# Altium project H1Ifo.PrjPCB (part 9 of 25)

## Sheet IfoIsc4.SchDoc: D1800185
size C; Engineer: Daniel Sigg; DocumentNumber: 8; Revision: 4; SheetNumber: 8; SheetTotal: 11
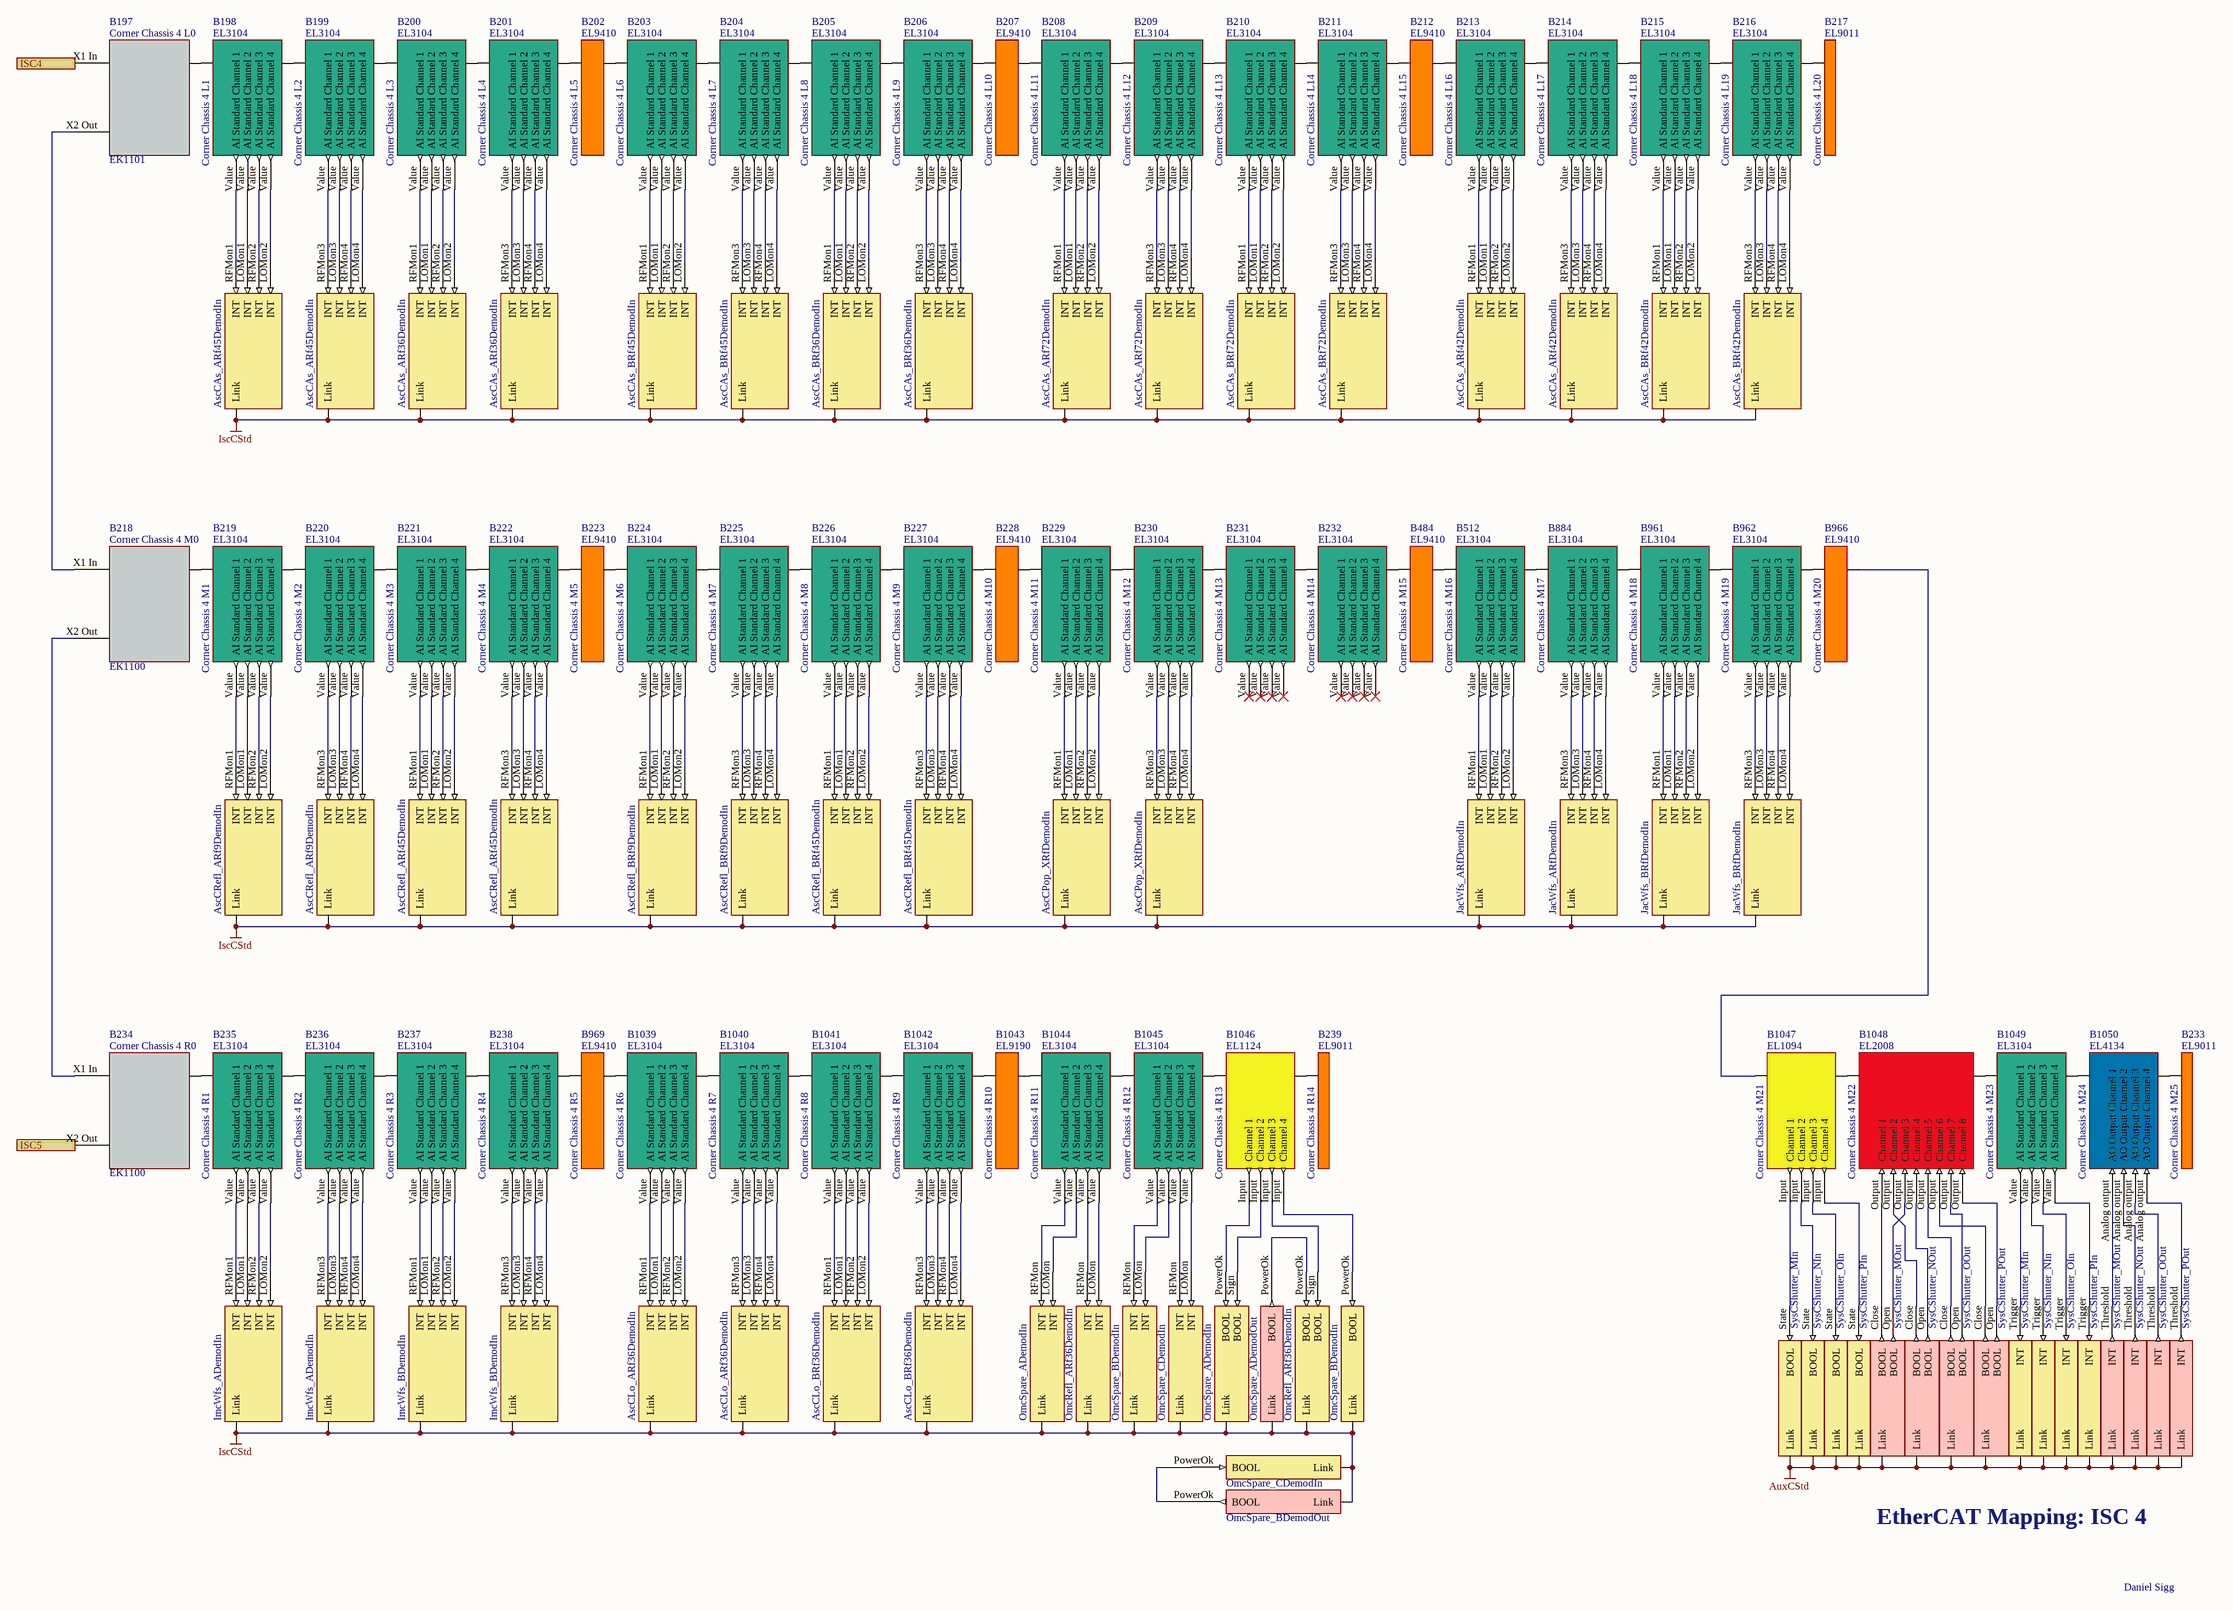
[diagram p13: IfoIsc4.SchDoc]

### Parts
B197  Corner Chassis 4 L0  Part Number: EK1101  (mechanical)
B198  Corner Chassis 4 L1  Part Number: EL3104  (mechanical)
B199  Corner Chassis 4 L2  Part Number: EL3104  (mechanical)
B200  Corner Chassis 4 L3  Part Number: EL3104  (mechanical)
B201  Corner Chassis 4 L4  Part Number: EL3104  (mechanical)
B202  Corner Chassis 4 L5  Part Number: EL9410  (mechanical)
B203  Corner Chassis 4 L6  Part Number: EL3104  (mechanical)
B204  Corner Chassis 4 L7  Part Number: EL3104  (mechanical)
B205  Corner Chassis 4 L8  Part Number: EL3104  (mechanical)
B206  Corner Chassis 4 L9  Part Number: EL3104  (mechanical)
B207  Corner Chassis 4 L10  Part Number: EL9410  (mechanical)
B208  Corner Chassis 4 L11  Part Number: EL3104  (mechanical)
B209  Corner Chassis 4 L12  Part Number: EL3104  (mechanical)
B210  Corner Chassis 4 L13  Part Number: EL3104  (mechanical)
B211  Corner Chassis 4 L14  Part Number: EL3104  (mechanical)
B212  Corner Chassis 4 L15  Part Number: EL9410  (mechanical)
B213  Corner Chassis 4 L16  Part Number: EL3104  (mechanical)
B214  Corner Chassis 4 L17  Part Number: EL3104  (mechanical)
B215  Corner Chassis 4 L18  Part Number: EL3104  (mechanical)
B216  Corner Chassis 4 L19  Part Number: EL3104  (mechanical)
B217  Corner Chassis 4 L20  Part Number: EL9011  (mechanical)
B218  Corner Chassis 4 M0  Part Number: EK1100  (mechanical)
B219  Corner Chassis 4 M1  Part Number: EL3104  (mechanical)
B220  Corner Chassis 4 M2  Part Number: EL3104  (mechanical)
B221  Corner Chassis 4 M3  Part Number: EL3104  (mechanical)
B222  Corner Chassis 4 M4  Part Number: EL3104  (mechanical)
B223  Corner Chassis 4 M5  Part Number: EL9410  (mechanical)
B224  Corner Chassis 4 M6  Part Number: EL3104  (mechanical)
B225  Corner Chassis 4 M7  Part Number: EL3104  (mechanical)
B226  Corner Chassis 4 M8  Part Number: EL3104  (mechanical)
B227  Corner Chassis 4 M9  Part Number: EL3104  (mechanical)
B228  Corner Chassis 4 M10  Part Number: EL9410  (mechanical)
B229  Corner Chassis 4 M11  Part Number: EL3104  (mechanical)
B230  Corner Chassis 4 M12  Part Number: EL3104  (mechanical)
B231  Corner Chassis 4 M13  Part Number: EL3104  (mechanical)
B232  Corner Chassis 4 M14  Part Number: EL3104  (mechanical)
B233  Corner Chassis 4 M25  Part Number: EL9011  (mechanical)
B234  Corner Chassis 4 R0  Part Number: EK1100  (mechanical)
B235  Corner Chassis 4 R1  Part Number: EL3104  (mechanical)
B236  Corner Chassis 4 R2  Part Number: EL3104  (mechanical)
B237  Corner Chassis 4 R3  Part Number: EL3104  (mechanical)
B238  Corner Chassis 4 R4  Part Number: EL3104  (mechanical)
B239  Corner Chassis 4 R14  Part Number: EL9011  (mechanical)
B484  Corner Chassis 4 M15  Part Number: EL9410  (mechanical)
B512  Corner Chassis 4 M16  Part Number: EL3104  (mechanical)
B884  Corner Chassis 4 M17  Part Number: EL3104  (mechanical)
B961  Corner Chassis 4 M18  Part Number: EL3104  (mechanical)
B962  Corner Chassis 4 M19  Part Number: EL3104  (mechanical)
B966  Corner Chassis 4 M20  Part Number: EL9410  (mechanical)
B969  Corner Chassis 4 R5  Part Number: EL9410  (mechanical)
B1039  Corner Chassis 4 R6  Part Number: EL3104  (mechanical)
B1040  Corner Chassis 4 R7  Part Number: EL3104  (mechanical)
B1041  Corner Chassis 4 R8  Part Number: EL3104  (mechanical)
B1042  Corner Chassis 4 R9  Part Number: EL3104  (mechanical)
B1043  Corner Chassis 4 R10  Part Number: EL9190  (mechanical)
B1044  Corner Chassis 4 R11  Part Number: EL3104  (mechanical)
B1045  Corner Chassis 4 R12  Part Number: EL3104  (mechanical)
B1046  Corner Chassis 4 R13  Part Number: EL1124  (mechanical)
B1047  Corner Chassis 4 M21  Part Number: EL1094  (mechanical)
B1048  Corner Chassis 4 M22  Part Number: EL2008  (mechanical)
B1049  Corner Chassis 4 M23  Part Number: EL3104  (mechanical)
B1050  Corner Chassis 4 M24  Part Number: EL4134  (mechanical)
V300  AscCAs_ARf45DemodIn  (parts A,B of 2)  (no BOM)
V301  AscCAs_ARf36DemodIn  (parts A,B of 2)  (no BOM)
V302  AscCAs_BRf45DemodIn  (parts A,B of 2)  (no BOM)
V321  AscCAs_BRf36DemodIn  (parts A,B of 2)  (no BOM)
V322  AscCAs_ARf72DemodIn  (parts A,B of 2)  (no BOM)
V323  AscCAs_BRf72DemodIn  (parts A,B of 2)  (no BOM)
V324  AscCAs_ARf42DemodIn  (parts A,B of 2)  (no BOM)
V326  AscCAs_BRf42DemodIn  (parts A,B of 2)  (no BOM)
V327  AscCRefl_ARf9DemodIn  (parts A,B of 2)  (no BOM)
V329  AscCRefl_ARf45DemodIn  (parts A,B of 2)  (no BOM)
V330  AscCRefl_BRf9DemodIn  (parts A,B of 2)  (no BOM)
V331  AscCRefl_BRf45DemodIn  (parts A,B of 2)  (no BOM)
V332  AscCPop_XRfDemodIn  (parts A,B of 2)  (no BOM)
V333  ImcWfs_ADemodIn  (parts A,B of 2)  (no BOM)
V334  ImcWfs_BDemodIn  (parts A,B of 2)  (no BOM)
V494  OmcSpare_ADemodOut  (no BOM)
V875  OmcSpare_BDemodOut  (no BOM)
V878  JacWfs_ARfDemodIn  (parts A,B of 2)  (no BOM)
V879  JacWfs_BRfDemodIn  (parts A,B of 2)  (no BOM)
V880  AscCLo_ARf36DemodIn  (parts A,B of 2)  (no BOM)
V881  AscCLo_BRf36DemodIn  (parts A,B of 2)  (no BOM)
V882  OmcSpare_ADemodIn  (parts A,B of 2)  (no BOM)
V883  OmcRefl_ARf36DemodIn  (parts A,B of 2)  (no BOM)
V884  OmcSpare_BDemodIn  (parts A,B of 2)  (no BOM)
V885  OmcSpare_CDemodIn  (parts A,B of 2)  (no BOM)
V886  SysCShutter_MIn  (parts A,B of 2)  (no BOM)
V887  SysCShutter_NIn  (parts A,B of 2)  (no BOM)
V888  SysCShutter_OIn  (parts A,B of 2)  (no BOM)
V889  SysCShutter_PIn  (parts A,B of 2)  (no BOM)
V890  SysCShutter_MOut  (parts A,B of 2)  (no BOM)
V891  SysCShutter_NOut  (parts A,B of 2)  (no BOM)
V892  SysCShutter_OOut  (parts A,B of 2)  (no BOM)
V893  SysCShutter_POut  (parts A,B of 2)  (no BOM)

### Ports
ISC4, ISC5

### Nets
AuxCStd: V886.0(Link) V886.1(Link) V887.0(Link) V887.1(Link) V888.0(Link) V888.1(Link) V889.0(Link) V889.1(Link) V890.0(Link) V890.1(Link) V891.0(Link) V891.1(Link) V892.0(Link) V892.1(Link) V893.0(Link) V893.1(Link)
IscCStd: V300.0(Link) V300.1(Link) V301.0(Link) V301.1(Link) V302.0(Link) V302.1(Link) V321.0(Link) V321.1(Link) V322.0(Link) V322.1(Link) V323.0(Link) V323.1(Link) V324.0(Link) V324.1(Link) V326.0(Link) V326.1(Link) V327.0(Link) V327.1(Link) V329.0(Link) V329.1(Link) V330.0(Link) V330.1(Link) V331.0(Link) V331.1(Link) V332.0(Link) V332.1(Link) V333.0(Link) V333.1(Link) V334.0(Link) V334.1(Link) V494.?1(Link) V875.?1(Link) V878.0(Link) V878.1(Link) V879.0(Link) V879.1(Link) V880.0(Link) V880.1(Link) V881.0(Link) V881.1(Link) V882.0(Link) V882.1(Link) V883.0(Link) V883.1(Link) V884.0(Link) V884.1(Link) V885.0(Link) V885.1(Link)
NetB175_X2 Out: B197.X1_In(A) ; port ISC4
NetB197_Ebus: B197.Ebus(B) B198.Ebus(A)
NetB197_X2 Out: B197.X2_Out(C) B218.X1_In(A)
NetB198_Ebus: B198.Ebus(B) B199.Ebus(A)
NetB198_Value: B198.Value(AI_Standard_Channel_1) V300.RFMon1(INT)
NetB198_Value: B198.Value(AI_Standard_Channel_2) V300.LOMon1(INT)  [a separate net that carries the same name]
NetB198_Value: B198.Value(AI_Standard_Channel_3) V300.RFMon2(INT)  [a separate net that carries the same name]
NetB198_Value: B198.Value(AI_Standard_Channel_4) V300.LOMon2(INT)  [a separate net that carries the same name]
NetB199_Ebus: B199.Ebus(B) B200.Ebus(A)
NetB199_Value: B199.Value(AI_Standard_Channel_1) V300.RFMon3(INT)
NetB199_Value: B199.Value(AI_Standard_Channel_2) V300.LOMon3(INT)  [a separate net that carries the same name]
NetB199_Value: B199.Value(AI_Standard_Channel_3) V300.RFMon4(INT)  [a separate net that carries the same name]
NetB199_Value: B199.Value(AI_Standard_Channel_4) V300.LOMon4(INT)  [a separate net that carries the same name]
NetB200_Ebus: B200.Ebus(B) B201.Ebus(A)
NetB200_Value: B200.Value(AI_Standard_Channel_1) V301.RFMon1(INT)
NetB200_Value: B200.Value(AI_Standard_Channel_2) V301.LOMon1(INT)  [a separate net that carries the same name]
NetB200_Value: B200.Value(AI_Standard_Channel_3) V301.RFMon2(INT)  [a separate net that carries the same name]
NetB200_Value: B200.Value(AI_Standard_Channel_4) V301.LOMon2(INT)  [a separate net that carries the same name]
NetB201_Ebus: B201.Ebus(B) B202.Ebus(A)
NetB201_Value: B201.Value(AI_Standard_Channel_1) V301.RFMon3(INT)
NetB201_Value: B201.Value(AI_Standard_Channel_2) V301.LOMon3(INT)  [a separate net that carries the same name]
NetB201_Value: B201.Value(AI_Standard_Channel_3) V301.RFMon4(INT)  [a separate net that carries the same name]
NetB201_Value: B201.Value(AI_Standard_Channel_4) V301.LOMon4(INT)  [a separate net that carries the same name]
NetB202_Ebus: B202.Ebus(B) B203.Ebus(A)
NetB203_Ebus: B203.Ebus(B) B204.Ebus(A)
NetB203_Value: B203.Value(AI_Standard_Channel_1) V302.RFMon1(INT)
NetB203_Value: B203.Value(AI_Standard_Channel_2) V302.LOMon1(INT)  [a separate net that carries the same name]
NetB203_Value: B203.Value(AI_Standard_Channel_3) V302.RFMon2(INT)  [a separate net that carries the same name]
NetB203_Value: B203.Value(AI_Standard_Channel_4) V302.LOMon2(INT)  [a separate net that carries the same name]
NetB204_Ebus: B204.Ebus(B) B205.Ebus(A)
NetB204_Value: B204.Value(AI_Standard_Channel_1) V302.RFMon3(INT)
NetB204_Value: B204.Value(AI_Standard_Channel_2) V302.LOMon3(INT)  [a separate net that carries the same name]
NetB204_Value: B204.Value(AI_Standard_Channel_3) V302.RFMon4(INT)  [a separate net that carries the same name]
NetB204_Value: B204.Value(AI_Standard_Channel_4) V302.LOMon4(INT)  [a separate net that carries the same name]
NetB205_Ebus: B205.Ebus(B) B206.Ebus(A)
NetB205_Value: B205.Value(AI_Standard_Channel_1) V321.RFMon1(INT)
NetB205_Value: B205.Value(AI_Standard_Channel_2) V321.LOMon1(INT)  [a separate net that carries the same name]
NetB205_Value: B205.Value(AI_Standard_Channel_3) V321.RFMon2(INT)  [a separate net that carries the same name]
NetB205_Value: B205.Value(AI_Standard_Channel_4) V321.LOMon2(INT)  [a separate net that carries the same name]
NetB206_Ebus: B206.Ebus(B) B207.Ebus(A)
NetB206_Value: B206.Value(AI_Standard_Channel_1) V321.RFMon3(INT)
NetB206_Value: B206.Value(AI_Standard_Channel_2) V321.LOMon3(INT)  [a separate net that carries the same name]
NetB206_Value: B206.Value(AI_Standard_Channel_3) V321.RFMon4(INT)  [a separate net that carries the same name]
NetB206_Value: B206.Value(AI_Standard_Channel_4) V321.LOMon4(INT)  [a separate net that carries the same name]
NetB207_Ebus: B207.Ebus(B) B208.Ebus(A)
NetB208_Ebus: B208.Ebus(B) B209.Ebus(A)
NetB208_Value: B208.Value(AI_Standard_Channel_1) V322.RFMon1(INT)
NetB208_Value: B208.Value(AI_Standard_Channel_2) V322.LOMon1(INT)  [a separate net that carries the same name]
NetB208_Value: B208.Value(AI_Standard_Channel_3) V322.RFMon2(INT)  [a separate net that carries the same name]
NetB208_Value: B208.Value(AI_Standard_Channel_4) V322.LOMon2(INT)  [a separate net that carries the same name]
NetB209_Ebus: B209.Ebus(B) B210.Ebus(A)
NetB209_Value: B209.Value(AI_Standard_Channel_1) V322.RFMon3(INT)
NetB209_Value: B209.Value(AI_Standard_Channel_2) V322.LOMon3(INT)  [a separate net that carries the same name]
NetB209_Value: B209.Value(AI_Standard_Channel_3) V322.RFMon4(INT)  [a separate net that carries the same name]
NetB209_Value: B209.Value(AI_Standard_Channel_4) V322.LOMon4(INT)  [a separate net that carries the same name]
NetB210_Ebus: B210.Ebus(B) B211.Ebus(A)
NetB210_Value: B210.Value(AI_Standard_Channel_1) V323.RFMon1(INT)
NetB210_Value: B210.Value(AI_Standard_Channel_2) V323.LOMon1(INT)  [a separate net that carries the same name]
NetB210_Value: B210.Value(AI_Standard_Channel_3) V323.RFMon2(INT)  [a separate net that carries the same name]
NetB210_Value: B210.Value(AI_Standard_Channel_4) V323.LOMon2(INT)  [a separate net that carries the same name]
NetB211_Ebus: B211.Ebus(B) B212.Ebus(A)
NetB211_Value: B211.Value(AI_Standard_Channel_1) V323.RFMon3(INT)
NetB211_Value: B211.Value(AI_Standard_Channel_2) V323.LOMon3(INT)  [a separate net that carries the same name]
NetB211_Value: B211.Value(AI_Standard_Channel_3) V323.RFMon4(INT)  [a separate net that carries the same name]
NetB211_Value: B211.Value(AI_Standard_Channel_4) V323.LOMon4(INT)  [a separate net that carries the same name]
NetB212_Ebus: B212.Ebus(B) B213.Ebus(A)
NetB213_Ebus: B213.Ebus(B) B214.Ebus(A)
NetB213_Value: B213.Value(AI_Standard_Channel_1) V324.RFMon1(INT)
NetB213_Value: B213.Value(AI_Standard_Channel_2) V324.LOMon1(INT)  [a separate net that carries the same name]
NetB213_Value: B213.Value(AI_Standard_Channel_3) V324.RFMon2(INT)  [a separate net that carries the same name]
NetB213_Value: B213.Value(AI_Standard_Channel_4) V324.LOMon2(INT)  [a separate net that carries the same name]
NetB214_Ebus: B214.Ebus(B) B215.Ebus(A)
NetB214_Value: B214.Value(AI_Standard_Channel_1) V324.RFMon3(INT)
NetB214_Value: B214.Value(AI_Standard_Channel_2) V324.LOMon3(INT)  [a separate net that carries the same name]
NetB214_Value: B214.Value(AI_Standard_Channel_3) V324.RFMon4(INT)  [a separate net that carries the same name]
NetB214_Value: B214.Value(AI_Standard_Channel_4) V324.LOMon4(INT)  [a separate net that carries the same name]
NetB215_Ebus: B215.Ebus(B) B216.Ebus(A)
NetB215_Value: B215.Value(AI_Standard_Channel_1) V326.RFMon1(INT)
NetB215_Value: B215.Value(AI_Standard_Channel_2) V326.LOMon1(INT)  [a separate net that carries the same name]
NetB215_Value: B215.Value(AI_Standard_Channel_3) V326.RFMon2(INT)  [a separate net that carries the same name]
NetB215_Value: B215.Value(AI_Standard_Channel_4) V326.LOMon2(INT)  [a separate net that carries the same name]
NetB216_Ebus: B216.Ebus(B) B217.Ebus(A)
NetB216_Value: B216.Value(AI_Standard_Channel_1) V326.RFMon3(INT)
NetB216_Value: B216.Value(AI_Standard_Channel_2) V326.LOMon3(INT)  [a separate net that carries the same name]
NetB216_Value: B216.Value(AI_Standard_Channel_3) V326.RFMon4(INT)  [a separate net that carries the same name]
NetB216_Value: B216.Value(AI_Standard_Channel_4) V326.LOMon4(INT)  [a separate net that carries the same name]
NetB218_Ebus: B218.Ebus(B) B219.Ebus(A)
NetB218_X2 Out: B218.X2_Out(C) B234.X1_In(A)
NetB219_Ebus: B219.Ebus(B) B220.Ebus(A)
NetB219_Value: B219.Value(AI_Standard_Channel_1) V327.RFMon1(INT)
NetB219_Value: B219.Value(AI_Standard_Channel_2) V327.LOMon1(INT)  [a separate net that carries the same name]
NetB219_Value: B219.Value(AI_Standard_Channel_3) V327.RFMon2(INT)  [a separate net that carries the same name]
NetB219_Value: B219.Value(AI_Standard_Channel_4) V327.LOMon2(INT)  [a separate net that carries the same name]
NetB220_Ebus: B220.Ebus(B) B221.Ebus(A)
NetB220_Value: B220.Value(AI_Standard_Channel_1) V327.RFMon3(INT)
NetB220_Value: B220.Value(AI_Standard_Channel_2) V327.LOMon3(INT)  [a separate net that carries the same name]
NetB220_Value: B220.Value(AI_Standard_Channel_3) V327.RFMon4(INT)  [a separate net that carries the same name]
NetB220_Value: B220.Value(AI_Standard_Channel_4) V327.LOMon4(INT)  [a separate net that carries the same name]
NetB221_Ebus: B221.Ebus(B) B222.Ebus(A)
NetB221_Value: B221.Value(AI_Standard_Channel_1) V329.RFMon1(INT)
NetB221_Value: B221.Value(AI_Standard_Channel_2) V329.LOMon1(INT)  [a separate net that carries the same name]
NetB221_Value: B221.Value(AI_Standard_Channel_3) V329.RFMon2(INT)  [a separate net that carries the same name]
NetB221_Value: B221.Value(AI_Standard_Channel_4) V329.LOMon2(INT)  [a separate net that carries the same name]
NetB222_Ebus: B222.Ebus(B) B223.Ebus(A)
NetB222_Value: B222.Value(AI_Standard_Channel_1) V329.RFMon3(INT)
NetB222_Value: B222.Value(AI_Standard_Channel_2) V329.LOMon3(INT)  [a separate net that carries the same name]
NetB222_Value: B222.Value(AI_Standard_Channel_3) V329.RFMon4(INT)  [a separate net that carries the same name]
NetB222_Value: B222.Value(AI_Standard_Channel_4) V329.LOMon4(INT)  [a separate net that carries the same name]
NetB223_Ebus: B223.Ebus(B) B224.Ebus(A)
NetB224_Ebus: B224.Ebus(B) B225.Ebus(A)
NetB224_Value: B224.Value(AI_Standard_Channel_1) V330.RFMon1(INT)
NetB224_Value: B224.Value(AI_Standard_Channel_2) V330.LOMon1(INT)  [a separate net that carries the same name]
NetB224_Value: B224.Value(AI_Standard_Channel_3) V330.RFMon2(INT)  [a separate net that carries the same name]
NetB224_Value: B224.Value(AI_Standard_Channel_4) V330.LOMon2(INT)  [a separate net that carries the same name]
NetB225_Ebus: B225.Ebus(B) B226.Ebus(A)
NetB225_Value: B225.Value(AI_Standard_Channel_1) V330.RFMon3(INT)
NetB225_Value: B225.Value(AI_Standard_Channel_2) V330.LOMon3(INT)  [a separate net that carries the same name]
NetB225_Value: B225.Value(AI_Standard_Channel_3) V330.RFMon4(INT)  [a separate net that carries the same name]
NetB225_Value: B225.Value(AI_Standard_Channel_4) V330.LOMon4(INT)  [a separate net that carries the same name]
NetB226_Ebus: B226.Ebus(B) B227.Ebus(A)
NetB226_Value: B226.Value(AI_Standard_Channel_1) V331.RFMon1(INT)
NetB226_Value: B226.Value(AI_Standard_Channel_2) V331.LOMon1(INT)  [a separate net that carries the same name]
NetB226_Value: B226.Value(AI_Standard_Channel_3) V331.RFMon2(INT)  [a separate net that carries the same name]
NetB226_Value: B226.Value(AI_Standard_Channel_4) V331.LOMon2(INT)  [a separate net that carries the same name]
NetB227_Ebus: B227.Ebus(B) B228.Ebus(A)
NetB227_Value: B227.Value(AI_Standard_Channel_1) V331.RFMon3(INT)
NetB227_Value: B227.Value(AI_Standard_Channel_2) V331.LOMon3(INT)  [a separate net that carries the same name]
NetB227_Value: B227.Value(AI_Standard_Channel_3) V331.RFMon4(INT)  [a separate net that carries the same name]
NetB227_Value: B227.Value(AI_Standard_Channel_4) V331.LOMon4(INT)  [a separate net that carries the same name]
NetB228_Ebus: B228.Ebus(B) B229.Ebus(A)
NetB229_Ebus: B229.Ebus(B) B230.Ebus(A)
NetB229_Value: B229.Value(AI_Standard_Channel_1) V332.RFMon1(INT)
NetB229_Value: B229.Value(AI_Standard_Channel_2) V332.LOMon1(INT)  [a separate net that carries the same name]
NetB229_Value: B229.Value(AI_Standard_Channel_3) V332.RFMon2(INT)  [a separate net that carries the same name]
NetB229_Value: B229.Value(AI_Standard_Channel_4) V332.LOMon2(INT)  [a separate net that carries the same name]
NetB230_Ebus: B230.Ebus(B) B231.Ebus(A)
NetB230_Value: B230.Value(AI_Standard_Channel_1) V332.RFMon3(INT)
NetB230_Value: B230.Value(AI_Standard_Channel_2) V332.LOMon3(INT)  [a separate net that carries the same name]
NetB230_Value: B230.Value(AI_Standard_Channel_3) V332.RFMon4(INT)  [a separate net that carries the same name]
NetB230_Value: B230.Value(AI_Standard_Channel_4) V332.LOMon4(INT)  [a separate net that carries the same name]
NetB231_Ebus: B231.Ebus(B) B232.Ebus(A)
NetB232_Ebus: B232.Ebus(B) B484.Ebus(A)
NetB233_Ebus: B233.Ebus(A) B1050.Ebus(B)
NetB234_Ebus: B234.Ebus(B) B235.Ebus(A)
NetB234_X2 Out: B234.X2_Out(C) ; port ISC5
NetB235_Ebus: B235.Ebus(B) B236.Ebus(A)
NetB235_Value: B235.Value(AI_Standard_Channel_1) V333.RFMon1(INT)
NetB235_Value: B235.Value(AI_Standard_Channel_2) V333.LOMon1(INT)  [a separate net that carries the same name]
NetB235_Value: B235.Value(AI_Standard_Channel_3) V333.RFMon2(INT)  [a separate net that carries the same name]
NetB235_Value: B235.Value(AI_Standard_Channel_4) V333.LOMon2(INT)  [a separate net that carries the same name]
NetB236_Ebus: B236.Ebus(B) B237.Ebus(A)
NetB236_Value: B236.Value(AI_Standard_Channel_1) V333.RFMon3(INT)
NetB236_Value: B236.Value(AI_Standard_Channel_2) V333.LOMon3(INT)  [a separate net that carries the same name]
NetB236_Value: B236.Value(AI_Standard_Channel_3) V333.RFMon4(INT)  [a separate net that carries the same name]
NetB236_Value: B236.Value(AI_Standard_Channel_4) V333.LOMon4(INT)  [a separate net that carries the same name]
NetB237_Ebus: B237.Ebus(B) B238.Ebus(A)
NetB237_Value: B237.Value(AI_Standard_Channel_1) V334.RFMon1(INT)
NetB237_Value: B237.Value(AI_Standard_Channel_2) V334.LOMon1(INT)  [a separate net that carries the same name]
NetB237_Value: B237.Value(AI_Standard_Channel_3) V334.RFMon2(INT)  [a separate net that carries the same name]
NetB237_Value: B237.Value(AI_Standard_Channel_4) V334.LOMon2(INT)  [a separate net that carries the same name]
NetB238_Ebus: B238.Ebus(B) B969.Ebus(A)
NetB238_Value: B238.Value(AI_Standard_Channel_1) V334.RFMon3(INT)
NetB238_Value: B238.Value(AI_Standard_Channel_2) V334.LOMon3(INT)  [a separate net that carries the same name]
NetB238_Value: B238.Value(AI_Standard_Channel_3) V334.RFMon4(INT)  [a separate net that carries the same name]
NetB238_Value: B238.Value(AI_Standard_Channel_4) V334.LOMon4(INT)  [a separate net that carries the same name]
NetB239_Ebus: B239.Ebus(A) B1046.Ebus(B)
NetB484_Ebus: B484.Ebus(B) B512.Ebus(A)
NetB512_Ebus: B512.Ebus(B) B884.Ebus(A)
NetB512_Value: B512.Value(AI_Standard_Channel_1) V878.RFMon1(INT)
NetB512_Value: B512.Value(AI_Standard_Channel_2) V878.LOMon1(INT)  [a separate net that carries the same name]
NetB512_Value: B512.Value(AI_Standard_Channel_3) V878.RFMon2(INT)  [a separate net that carries the same name]
NetB512_Value: B512.Value(AI_Standard_Channel_4) V878.LOMon2(INT)  [a separate net that carries the same name]
NetB884_Ebus: B884.Ebus(B) B961.Ebus(A)
NetB884_Value: B884.Value(AI_Standard_Channel_1) V878.RFMon3(INT)
NetB884_Value: B884.Value(AI_Standard_Channel_2) V878.LOMon3(INT)  [a separate net that carries the same name]
NetB884_Value: B884.Value(AI_Standard_Channel_3) V878.RFMon4(INT)  [a separate net that carries the same name]
NetB884_Value: B884.Value(AI_Standard_Channel_4) V878.LOMon4(INT)  [a separate net that carries the same name]
NetB961_Ebus: B961.Ebus(B) B962.Ebus(A)
NetB961_Value: B961.Value(AI_Standard_Channel_1) V879.RFMon1(INT)
NetB961_Value: B961.Value(AI_Standard_Channel_2) V879.LOMon1(INT)  [a separate net that carries the same name]
NetB961_Value: B961.Value(AI_Standard_Channel_3) V879.RFMon2(INT)  [a separate net that carries the same name]
NetB961_Value: B961.Value(AI_Standard_Channel_4) V879.LOMon2(INT)  [a separate net that carries the same name]
NetB962_Ebus: B962.Ebus(B) B966.Ebus(A)
NetB962_Value: B962.Value(AI_Standard_Channel_1) V879.RFMon3(INT)
NetB962_Value: B962.Value(AI_Standard_Channel_2) V879.LOMon3(INT)  [a separate net that carries the same name]
NetB962_Value: B962.Value(AI_Standard_Channel_3) V879.RFMon4(INT)  [a separate net that carries the same name]
NetB962_Value: B962.Value(AI_Standard_Channel_4) V879.LOMon4(INT)  [a separate net that carries the same name]
NetB966_Ebus: B966.Ebus(B) B1047.Ebus(A)
NetB969_Ebus: B969.Ebus(B) B1039.Ebus(A)
NetB1039_Ebus: B1039.Ebus(B) B1040.Ebus(A)
NetB1039_Value: B1039.Value(AI_Standard_Channel_1) V880.RFMon1(INT)
NetB1039_Value: B1039.Value(AI_Standard_Channel_2) V880.LOMon1(INT)  [a separate net that carries the same name]
NetB1039_Value: B1039.Value(AI_Standard_Channel_3) V880.RFMon2(INT)  [a separate net that carries the same name]
NetB1039_Value: B1039.Value(AI_Standard_Channel_4) V880.LOMon2(INT)  [a separate net that carries the same name]
NetB1040_Ebus: B1040.Ebus(B) B1041.Ebus(A)
NetB1040_Value: B1040.Value(AI_Standard_Channel_1) V880.RFMon3(INT)
NetB1040_Value: B1040.Value(AI_Standard_Channel_2) V880.LOMon3(INT)  [a separate net that carries the same name]
NetB1040_Value: B1040.Value(AI_Standard_Channel_3) V880.RFMon4(INT)  [a separate net that carries the same name]
NetB1040_Value: B1040.Value(AI_Standard_Channel_4) V880.LOMon4(INT)  [a separate net that carries the same name]
NetB1041_Ebus: B1041.Ebus(B) B1042.Ebus(A)
NetB1041_Value: B1041.Value(AI_Standard_Channel_1) V881.RFMon1(INT)
NetB1041_Value: B1041.Value(AI_Standard_Channel_2) V881.LOMon1(INT)  [a separate net that carries the same name]
NetB1041_Value: B1041.Value(AI_Standard_Channel_3) V881.RFMon2(INT)  [a separate net that carries the same name]
NetB1041_Value: B1041.Value(AI_Standard_Channel_4) V881.LOMon2(INT)  [a separate net that carries the same name]
NetB1042_Ebus: B1042.Ebus(B) B1043.Ebus(A)
NetB1042_Value: B1042.Value(AI_Standard_Channel_1) V881.RFMon3(INT)
NetB1042_Value: B1042.Value(AI_Standard_Channel_2) V881.LOMon3(INT)  [a separate net that carries the same name]
NetB1042_Value: B1042.Value(AI_Standard_Channel_3) V881.RFMon4(INT)  [a separate net that carries the same name]
NetB1042_Value: B1042.Value(AI_Standard_Channel_4) V881.LOMon4(INT)  [a separate net that carries the same name]
NetB1043_Ebus: B1043.Ebus(B) B1044.Ebus(A)
NetB1044_Ebus: B1044.Ebus(B) B1045.Ebus(A)
NetB1044_Value: B1044.Value(AI_Standard_Channel_1) V882.RFMon(INT)
NetB1044_Value: B1044.Value(AI_Standard_Channel_2) V882.LOMon(INT)  [a separate net that carries the same name]
NetB1044_Value: B1044.Value(AI_Standard_Channel_3) V883.RFMon(INT)  [a separate net that carries the same name]
NetB1044_Value: B1044.Value(AI_Standard_Channel_4) V883.LOMon(INT)  [a separate net that carries the same name]
NetB1045_Ebus: B1045.Ebus(B) B1046.Ebus(A)
NetB1045_Value: B1045.Value(AI_Standard_Channel_1) V884.RFMon(INT)
NetB1045_Value: B1045.Value(AI_Standard_Channel_2) V884.LOMon(INT)  [a separate net that carries the same name]
NetB1045_Value: B1045.Value(AI_Standard_Channel_3) V885.RFMon(INT)  [a separate net that carries the same name]
NetB1045_Value: B1045.Value(AI_Standard_Channel_4) V885.LOMon(INT)  [a separate net that carries the same name]
NetB1046_Input: B1046.Input(Channel_1) V882.PowerOk(BOOL)
NetB1046_Input: B1046.Input(Channel_2) V882.Sign(BOOL)  [a separate net that carries the same name]
NetB1046_Input: B1046.Input(Channel_3) V883.Sign(BOOL)  [a separate net that carries the same name]
NetB1046_Input: B1046.Input(Channel_4) V884.PowerOk(BOOL)  [a separate net that carries the same name]
NetB1047_Ebus: B1047.Ebus(B) B1048.Ebus(A)
NetB1047_Input: B1047.Input(Channel_1) V886.State(BOOL)
NetB1047_Input: B1047.Input(Channel_2) V887.State(BOOL)  [a separate net that carries the same name]
NetB1047_Input: B1047.Input(Channel_3) V888.State(BOOL)  [a separate net that carries the same name]
NetB1047_Input: B1047.Input(Channel_4) V889.State(BOOL)  [a separate net that carries the same name]
NetB1048_Ebus: B1048.Ebus(B) B1049.Ebus(A)
NetB1048_Output: B1048.Output(Channel_1) V890.Close(BOOL)
NetB1048_Output: B1048.Output(Channel_2) V891.Close(BOOL)  [a separate net that carries the same name]
NetB1048_Output: B1048.Output(Channel_3) V890.Open(BOOL)  [a separate net that carries the same name]
NetB1048_Output: B1048.Output(Channel_4) V891.Open(BOOL)  [a separate net that carries the same name]
NetB1048_Output: B1048.Output(Channel_5) V892.Close(BOOL)  [a separate net that carries the same name]
NetB1048_Output: B1048.Output(Channel_6) V893.Close(BOOL)  [a separate net that carries the same name]
NetB1048_Output: B1048.Output(Channel_7) V892.Open(BOOL)  [a separate net that carries the same name]
NetB1048_Output: B1048.Output(Channel_8) V893.Open(BOOL)  [a separate net that carries the same name]
NetB1049_Ebus: B1049.Ebus(B) B1050.Ebus(A)
NetB1049_Value: B1049.Value(AI_Standard_Channel_1) V886.Trigger(INT)
NetB1049_Value: B1049.Value(AI_Standard_Channel_2) V887.Trigger(INT)  [a separate net that carries the same name]
NetB1049_Value: B1049.Value(AI_Standard_Channel_3) V888.Trigger(INT)  [a separate net that carries the same name]
NetB1049_Value: B1049.Value(AI_Standard_Channel_4) V889.Trigger(INT)  [a separate net that carries the same name]
NetB1050_Analog output: B1050.Analog_output(AO_Output_Channel_1) V890.Threshold(INT)
NetB1050_Analog output: B1050.Analog_output(AO_Output_Channel_2) V891.Threshold(INT)  [a separate net that carries the same name]
NetB1050_Analog output: B1050.Analog_output(AO_Output_Channel_3) V892.Threshold(INT)  [a separate net that carries the same name]
NetB1050_Analog output: B1050.Analog_output(AO_Output_Channel_4) V893.Threshold(INT)  [a separate net that carries the same name]
NetV494_PowerOk: V494.PowerOk(BOOL) V883.PowerOk(BOOL)
NetV875_PowerOk: V875.PowerOk(BOOL) V885.PowerOk(BOOL)

Not connected (* = marked no-connect by the designer): B231 Value(AI_Standard_Channel_1)*; B232 Value(AI_Standard_Channel_1)*

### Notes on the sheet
- EtherCAT Mapping: ISC 4
- Daniel Sigg

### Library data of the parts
B197 = CouplerEK1101: EtherCAT Coupler; Rail: Left; BoxNextB: IRGKQKYA; BoxNextC: MMNIINJF; BoxPrev: DISNVYMV; PortPrevFull: 1134/C; PortPrevShort: C 'X2 Out'; Fullname: TIID^Vertex ISC (EtherCAT)^Corner Chassis 4 L0 (EK1101); BoxPorts: Junction; BoxAddr: 1153; Disabled: False
B198 = TerminalEL3104: EtherCAT Terminal EL3104 4-chn Analog Input; Rail: Left; BoxNextB: DQNKWSCF; BoxPrev: YKWNQAOF; PortPrevFull: 1153/B; PortPrevShort: B; Fullname: TIID^Vertex ISC (EtherCAT)^Corner Chassis 4 L0 (EK1101)^Corner Chassis 4 L1 (EL3104); BoxAddr: 1154; Disabled: False
B199 = TerminalEL3104: EtherCAT Terminal EL3104 4-chn Analog Input; Rail: Left; BoxNextB: TADXUTLW; BoxPrev: IRGKQKYA; PortPrevFull: 1154/B; PortPrevShort: B; Fullname: TIID^Vertex ISC (EtherCAT)^Corner Chassis 4 L0 (EK1101)^Corner Chassis 4 L2 (EL3104); BoxAddr: 1155; Disabled: False
B200 = TerminalEL3104: EtherCAT Terminal EL3104 4-chn Analog Input; Rail: Left; BoxNextB: LMVFSTSA; BoxPrev: DQNKWSCF; PortPrevFull: 1155/B; PortPrevShort: B; Fullname: TIID^Vertex ISC (EtherCAT)^Corner Chassis 4 L0 (EK1101)^Corner Chassis 4 L3 (EL3104); BoxAddr: 1156; Disabled: False
B201 = TerminalEL3104: EtherCAT Terminal EL3104 4-chn Analog Input; Rail: Left; BoxNextB: THQIIDHL; BoxPrev: TADXUTLW; PortPrevFull: 1156/B; PortPrevShort: B; Fullname: TIID^Vertex ISC (EtherCAT)^Corner Chassis 4 L0 (EK1101)^Corner Chassis 4 L4 (EL3104); BoxAddr: 1157; Disabled: False
B202 B207 B212 = TerminalEL9410: EtherCAT Terminal EL9410 Power; Rail: Left; BoxNextB: CGWBNFDW; BoxPrev: XWFYBRPV; PortPrevFull: 1161/B; PortPrevShort: B; Fullname: TIID^Vertex ISC (EtherCAT)^Corner Chassis 4 L0 (EK1101)^Corner Chassis 4 L10 (EL9410); BoxAddr: 1162; Disabled: False
B203 = TerminalEL3104: EtherCAT Terminal EL3104 4-chn Analog Input; Rail: Left; BoxNextB: CWCPLCXA; BoxPrev: THQIIDHL; PortPrevFull: 1157/B; PortPrevShort: B; Fullname: TIID^Vertex ISC (EtherCAT)^Corner Chassis 4 L0 (EK1101)^Corner Chassis 4 L6 (EL3104); BoxAddr: 1158; Disabled: False
B204 = TerminalEL3104: EtherCAT Terminal EL3104 4-chn Analog Input; Rail: Left; BoxNextB: MSORJDLH; BoxPrev: WTOICCIA; PortPrevFull: 1158/B; PortPrevShort: B; Fullname: TIID^Vertex ISC (EtherCAT)^Corner Chassis 4 L0 (EK1101)^Corner Chassis 4 L7 (EL3104); BoxAddr: 1159; Disabled: False
B205 = TerminalEL3104: EtherCAT Terminal EL3104 4-chn Analog Input; Rail: Left; BoxNextB: XWFYBRPV; BoxPrev: CWCPLCXA; PortPrevFull: 1159/B; PortPrevShort: B; Fullname: TIID^Vertex ISC (EtherCAT)^Corner Chassis 4 L0 (EK1101)^Corner Chassis 4 L8 (EL3104); BoxAddr: 1160; Disabled: False
B206 = TerminalEL3104: EtherCAT Terminal EL3104 4-chn Analog Input; Rail: Left; BoxNextB: DGPRQBVX; BoxPrev: MSORJDLH; PortPrevFull: 1160/B; PortPrevShort: B; Fullname: TIID^Vertex ISC (EtherCAT)^Corner Chassis 4 L0 (EK1101)^Corner Chassis 4 L9 (EL3104); BoxAddr: 1161; Disabled: False
B208 = TerminalEL3104: EtherCAT Terminal EL3104 4-chn Analog Input; Rail: Left; BoxNextB: EPSPNJHV; BoxPrev: DGPRQBVX; PortPrevFull: 1162/B; PortPrevShort: B; Fullname: TIID^Vertex ISC (EtherCAT)^Corner Chassis 4 L0 (EK1101)^Corner Chassis 4 L11 (EL3104); BoxAddr: 1163; Disabled: False
B209 = TerminalEL3104: EtherCAT Terminal EL3104 4-chn Analog Input; Rail: Left; BoxNextB: PLJMPCCB; BoxPrev: CGWBNFDW; PortPrevFull: 1163/B; PortPrevShort: B; Fullname: TIID^Vertex ISC (EtherCAT)^Corner Chassis 4 L0 (EK1101)^Corner Chassis 4 L12 (EL3104); BoxAddr: 1164; Disabled: False
B210 = TerminalEL3104: EtherCAT Terminal EL3104 4-chn Analog Input; Rail: Left; BoxNextB: DGMJVBGJ; BoxPrev: EPSPNJHV; PortPrevFull: 1164/B; PortPrevShort: B; Fullname: TIID^Vertex ISC (EtherCAT)^Corner Chassis 4 L0 (EK1101)^Corner Chassis 4 L13 (EL3104); BoxAddr: 1165; Disabled: False
B211 = TerminalEL3104: EtherCAT Terminal EL3104 4-chn Analog Input; Rail: Left; BoxNextB: QQPRCIBY; BoxPrev: PLJMPCCB; PortPrevFull: 1165/B; PortPrevShort: B; Fullname: TIID^Vertex ISC (EtherCAT)^Corner Chassis 4 L0 (EK1101)^Corner Chassis 4 L14 (EL3104); BoxAddr: 1166; Disabled: False
B213 = TerminalEL3104: EtherCAT Terminal EL3104 4-chn Analog Input; Rail: Left; BoxNextB: IQOBSTDL; BoxPrev: QQPRCIBY; PortPrevFull: 1166/B; PortPrevShort: B; Fullname: TIID^Vertex ISC (EtherCAT)^Corner Chassis 4 L0 (EK1101)^Corner Chassis 4 L16 (EL3104); BoxAddr: 1167; Disabled: False
B214 = TerminalEL3104: EtherCAT Terminal EL3104 4-chn Analog Input; Rail: Left; BoxNextB: QEPTPBGN; BoxPrev: LULPDUJP; PortPrevFull: 1167/B; PortPrevShort: B; Fullname: TIID^Vertex ISC (EtherCAT)^Corner Chassis 4 L0 (EK1101)^Corner Chassis 4 L17 (EL3104); BoxAddr: 1168; Disabled: False
B215 = TerminalEL3104: EtherCAT Terminal EL3104 4-chn Analog Input; Rail: Left; BoxNextB: VSRORLKR; BoxPrev: IQOBSTDL; PortPrevFull: 1168/B; PortPrevShort: B; Fullname: TIID^Vertex ISC (EtherCAT)^Corner Chassis 4 L0 (EK1101)^Corner Chassis 4 L18 (EL3104); BoxAddr: 1169; Disabled: False
B216 = TerminalEL3104: EtherCAT Terminal EL3104 4-chn Analog Input; Rail: Left; BoxNextB: HTPFDEUL; BoxPrev: QEPTPBGN; PortPrevFull: 1169/B; PortPrevShort: B; Fullname: TIID^Vertex ISC (EtherCAT)^Corner Chassis 4 L0 (EK1101)^Corner Chassis 4 L19 (EL3104); BoxAddr: 1170; Disabled: False
B217 = TerminalEL9011: EtherCAT Terminal EL9011 End; BoxType: TerminalPassive; Rail: Left; BoxPrev: VSRORLKR; PortPrevShort: B; Fullname: TIID^Vertex ISC (EtherCAT)^Corner Chassis 4 L0 (EK1101)^Corner Chassis 4 L20 (EL9011); Disabled: False
B218 = CouplerEK1100: EtherCAT Coupler; Rail: Middle; BoxNextB: EXOFERFG; BoxNextC: YDPMJXXR; BoxPrev: YKWNQAOF; PortPrevFull: 1153/C; PortPrevShort: C 'X2 Out'; Fullname: TIID^Vertex ISC (EtherCAT)^Corner Chassis 4 M0 (EK1100); BoxPorts: Junction; BoxAddr: 1171; Disabled: False
B219 = TerminalEL3104: EtherCAT Terminal EL3104 4-chn Analog Input; Rail: Middle; BoxNextB: PCNADATP; BoxPrev: MMNIINJF; PortPrevFull: 1171/B; PortPrevShort: B; Fullname: TIID^Vertex ISC (EtherCAT)^Corner Chassis 4 M0 (EK1100)^Corner Chassis 4 M1 (EL3104); BoxAddr: 1172; Disabled: False
B220 = TerminalEL3104: EtherCAT Terminal EL3104 4-chn Analog Input; Rail: Middle; BoxNextB: GLSOVTQF; BoxPrev: EXOFERFG; PortPrevFull: 1172/B; PortPrevShort: B; Fullname: TIID^Vertex ISC (EtherCAT)^Corner Chassis 4 M0 (EK1100)^Corner Chassis 4 M2 (EL3104); BoxAddr: 1173; Disabled: False
B221 = TerminalEL3104: EtherCAT Terminal EL3104 4-chn Analog Input; Rail: Middle; BoxNextB: NACTFJPE; BoxPrev: PCNADATP; PortPrevFull: 1173/B; PortPrevShort: B; Fullname: TIID^Vertex ISC (EtherCAT)^Corner Chassis 4 M0 (EK1100)^Corner Chassis 4 M3 (EL3104); BoxAddr: 1174; Disabled: False
B222 = TerminalEL3104: EtherCAT Terminal EL3104 4-chn Analog Input; Rail: Middle; BoxNextB: KYQMILKW; BoxPrev: GLSOVTQF; PortPrevFull: 1174/B; PortPrevShort: B; Fullname: TIID^Vertex ISC (EtherCAT)^Corner Chassis 4 M0 (EK1100)^Corner Chassis 4 M4 (EL3104); BoxAddr: 1175; Disabled: False
B223 B228 B484 B966 B969 = TerminalEL9410: EtherCAT Terminal EL9410 Power; Rail: Middle; BoxNextB: MANUKDUB; BoxPrev: VILQHKDO; PortPrevFull: 1179/B; PortPrevShort: B; Fullname: TIID^Vertex ISC (EtherCAT)^Corner Chassis 4 M0 (EK1100)^Corner Chassis 4 M10 (EL9410); BoxAddr: 1180; Disabled: False
B224 B1039 = TerminalEL3104: EtherCAT Terminal EL3104 4-chn Analog Input; Rail: Middle; BoxNextB: HRRYATQS; BoxPrev: KYQMILKW; PortPrevFull: 1175/B; PortPrevShort: B; Fullname: TIID^Vertex ISC (EtherCAT)^Corner Chassis 4 M0 (EK1100)^Corner Chassis 4 M6 (EL3104); BoxAddr: 1176; Disabled: False
B225 B1040 = TerminalEL3104: EtherCAT Terminal EL3104 4-chn Analog Input; Rail: Middle; BoxNextB: RFTRKPHK; BoxPrev: AYMITKJK; PortPrevFull: 1176/B; PortPrevShort: B; Fullname: TIID^Vertex ISC (EtherCAT)^Corner Chassis 4 M0 (EK1100)^Corner Chassis 4 M7 (EL3104); BoxAddr: 1177; Disabled: False
B226 B1041 B1044 = TerminalEL3104: EtherCAT Terminal EL3104 4-chn Analog Input; Rail: Middle; BoxNextB: VILQHKDO; BoxPrev: HRRYATQS; PortPrevFull: 1177/B; PortPrevShort: B; Fullname: TIID^Vertex ISC (EtherCAT)^Corner Chassis 4 M0 (EK1100)^Corner Chassis 4 M8 (EL3104); BoxAddr: 1178; Disabled: False
B227 B1042 B1045 = TerminalEL3104: EtherCAT Terminal EL3104 4-chn Analog Input; Rail: Middle; BoxNextB: CTKHWEQP; BoxPrev: RFTRKPHK; PortPrevFull: 1178/B; PortPrevShort: B; Fullname: TIID^Vertex ISC (EtherCAT)^Corner Chassis 4 M0 (EK1100)^Corner Chassis 4 M9 (EL3104); BoxAddr: 1179; Disabled: False
B229 B512 = TerminalEL3104: EtherCAT Terminal EL3104 4-chn Analog Input; Rail: Middle; BoxNextB: CSDNENSF; BoxPrev: CTKHWEQP; PortPrevFull: 1180/B; PortPrevShort: B; Fullname: TIID^Vertex ISC (EtherCAT)^Corner Chassis 4 M0 (EK1100)^Corner Chassis 4 M11 (EL3104); BoxAddr: 1181; Disabled: False
B230 B884 = TerminalEL3104: EtherCAT Terminal EL3104 4-chn Analog Input; Rail: Middle; BoxNextB: SLIVPLEU; BoxPrev: MANUKDUB; PortPrevFull: 1181/B; PortPrevShort: B; Fullname: TIID^Vertex ISC (EtherCAT)^Corner Chassis 4 M0 (EK1100)^Corner Chassis 4 M12 (EL3104); BoxAddr: 1182; Disabled: False
B231 B961 = TerminalEL3104: EtherCAT Terminal EL3104 4-chn Analog Input; Rail: Middle; BoxNextB: SMFYHIJX; BoxPrev: CSDNENSF; PortPrevFull: 1182/B; PortPrevShort: B; Fullname: TIID^Vertex ISC (EtherCAT)^Corner Chassis 4 M0 (EK1100)^Corner Chassis 4 M13 (EL3104); BoxAddr: 1183; Disabled: False
B232 B962 B1049 = TerminalEL3104: EtherCAT Terminal EL3104 4-chn Analog Input; Rail: Middle; BoxNextB: PGIPFMSE; BoxPrev: SLIVPLEU; PortPrevFull: 1183/B; PortPrevShort: B; Fullname: TIID^Vertex ISC (EtherCAT)^Corner Chassis 4 M0 (EK1100)^Corner Chassis 4 M14 (EL3104); BoxAddr: 1184; Disabled: False
B233 = TerminalEL9011: EtherCAT Terminal EL9011 End; BoxType: TerminalPassive; Rail: Middle; BoxPrev: SMFYHIJX; PortPrevShort: B; Fullname: TIID^Vertex ISC (EtherCAT)^Corner Chassis 4 M0 (EK1100)^Corner Chassis 4 M15 (EL9011); Disabled: False
B234 = CouplerEK1100: EtherCAT Coupler; Rail: Right; BoxNextB: GLSLHGFW; BoxNextC: FCKUDXRC; BoxPrev: MMNIINJF; PortPrevFull: 1171/C; PortPrevShort: C 'X2 Out'; Fullname: TIID^Vertex ISC (EtherCAT)^Corner Chassis 4 R0 (EK1100); BoxPorts: Junction; BoxAddr: 1185; Disabled: False
B235 = TerminalEL3104: EtherCAT Terminal EL3104 4-chn Analog Input; Rail: Right; BoxNextB: APIJKXMM; BoxPrev: YDPMJXXR; PortPrevFull: 1185/B; PortPrevShort: B; Fullname: TIID^Vertex ISC (EtherCAT)^Corner Chassis 4 R0 (EK1100)^Corner Chassis 4 R1 (EL3104); BoxAddr: 1186; Disabled: False
B236 = TerminalEL3104: EtherCAT Terminal EL3104 4-chn Analog Input; Rail: Right; BoxNextB: WJTXISCD; BoxPrev: GLSLHGFW; PortPrevFull: 1186/B; PortPrevShort: B; Fullname: TIID^Vertex ISC (EtherCAT)^Corner Chassis 4 R0 (EK1100)^Corner Chassis 4 R2 (EL3104); BoxAddr: 1187; Disabled: False
B237 = TerminalEL3104: EtherCAT Terminal EL3104 4-chn Analog Input; Rail: Right; BoxNextB: TXKDSBLU; BoxPrev: APIJKXMM; PortPrevFull: 1187/B; PortPrevShort: B; Fullname: TIID^Vertex ISC (EtherCAT)^Corner Chassis 4 R0 (EK1100)^Corner Chassis 4 R3 (EL3104); BoxAddr: 1188; Disabled: False
B238 = TerminalEL3104: EtherCAT Terminal EL3104 4-chn Analog Input; Rail: Right; BoxNextB: SCGCHNEM; BoxPrev: WJTXISCD; PortPrevFull: 1188/B; PortPrevShort: B; Fullname: TIID^Vertex ISC (EtherCAT)^Corner Chassis 4 R0 (EK1100)^Corner Chassis 4 R4 (EL3104); BoxAddr: 1189; Disabled: False
B239 = TerminalEL9011: EtherCAT Terminal EL9011 End; BoxType: TerminalPassive; Rail: Right; BoxPrev: TXKDSBLU; PortPrevShort: B; Fullname: TIID^Vertex ISC (EtherCAT)^Corner Chassis 4 R0 (EK1100)^Corner Chassis 4 R5 (EL9011); Disabled: False
B1043 = TerminalEL9190: EtherCAT Terminal EL9190 Supply; BoxType: TerminalPassive; Rail: Middle; BoxNextB: NIFPYAGY; BoxPrev: AWJEIRBS; PortPrevShort: B; Fullname: TIID^Vertex ISC (EtherCAT)^Corner Chassis 5 M0 (EK1100)^Corner Chassis 5 M8 (EL9190); Disabled: False
B1046 = TerminalEL1124: EtherCAT Terminal EL1124 4-chn Digital Input; Rail: Left; BoxNextB: HTAQRIMN; BoxPrev: HRPNLCIR; PortPrevFull: 1113/B; PortPrevShort: B; Fullname: TIID^Vertex ISC (EtherCAT)^Corner Chassis 3 L0 (EK1101)^Corner Chassis 3 L4 (EL1124); BoxAddr: 1114; Disabled: False
B1047 = TerminalEL1094: EtherCAT Terminal EL1094 4-channel digital input terminal 24 V DC, switching to negative potential; Rail: Left; BoxNextB: DNPLFSLH; BoxPrev: NRTAXIAP; PortPrevFull: 1012/B; PortPrevShort: B; Fullname: TIID^Vertex PSL TCS (EtherCAT)^PSL IO TCS Chassis R0 (EK1101)^PSL IO TCS Chassis R9 (EK1122)^PSL IO TCS Chassis L0 (EK1101)^PSL IO TCS Chassis L3 (EL1094); BoxAddr: 1013; Disabled: False
B1048 = TerminalEL2008: EtherCAT Terminal EL2008 8-channel digital output terminal 24 V DC, 0.5 A; Rail: Right; BoxNextB: REGWBYFR; BoxPrev: QWHNWNKG; PortPrevFull: 1243/B; PortPrevShort: B; Fullname: TIID^Vertex Squeezer (EtherCAT)^SQZ Chassis 4 R0 (EK1100)^SQZ Chassis 4 R4 (EL2008); BoxAddr: 1244; Disabled: False
B1050 = TerminalEL4134: EtherCAT Terminal EL4134 4-chn Analog Ouput; Rail: Right; BoxNextB: ICNHSMEO; BoxPrev: JULUELOO; PortPrevFull: 1231/B; PortPrevShort: B; Fullname: TIID^Vertex ISC (EtherCAT)^Corner Chassis 5 R0 (EK1100)^Corner Chassis 5 R11 (EL4134); BoxAddr: 1232; Disabled: False
V300-V302 V321-V324 V326 V327 V329-V334 V878-V881 = Demodulator_DemodulatorQuadInStruct: DemodulatorQuadInStruct; BoxType: Variable; Instance: H1IscCorner Instance; PLC: H1IscCorner; Task: IscCStd
V494 V875 = Demodulator_DemodulatorOutStruct: DemodulatorOutStruct; BoxType: Variable; Instance: H1IscCorner Instance; PLC: H1IscCorner; Task: IscCStd
V882 V883 = Demodulator_DemodulatorInStructSign: DemodulatorInStruct; BoxType: Variable; Instance: H1IscCorner Instance; PLC: H1IscCorner; Task: IscCStd
V884 V885 = Demodulator_DemodulatorInStructOk: DemodulatorInStruct; BoxType: Variable; Instance: H1IscCorner Instance; PLC: H1IscCorner; Task: IscCStd
V886-V889 = ShutterControl_ShutterControlInStruct: ShutterControlInStruct; BoxType: Variable; Instance: H1AuxCorner Instance; PLC: H1AuxCorner; Task: AuxCStd
V890-V893 = ShutterControl_ShutterControlOutStruct: ShutterControlOutStruct; BoxType: Variable; Instance: H1AuxCorner Instance; PLC: H1AuxCorner; Task: AuxCStd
